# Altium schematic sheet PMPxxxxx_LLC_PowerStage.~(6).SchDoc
size 431 x 279 mm; Date: Not shown in title block; ApprovedBy: Not shown in title block; CheckedBy: Not shown in title block; Author: Not shown in title block; CompanyName: Not shown in title block; Engineer: Not shown in title block; Organization: Not shown in title block; Address1: Not shown in title block; Address2: Not shown in title block; Address3: Not shown in title block; Address4: Not shown in title block; DocumentNumber: 2; Revision: Use project parameter SCH_Rev; SheetNumber: 2; SheetTotal: 4; PageSetup: Record=PageOptions¦CenterHorizontal=True¦CenterVertical=True¦PrintScale=1.00¦XCorrection=1.00¦YCorrection=1.00¦PrintKind=0¦BorderSize=5000000¦LeftOffset=0¦BottomOffset=0¦Orientation=2¦PaperLength=1000¦PaperWidth=1000¦Scale=100¦PaperSource=15¦PrintQuality=600¦MediaType=1¦DitherType=10¦PaperKind=Letter¦PrintScaleMode=1
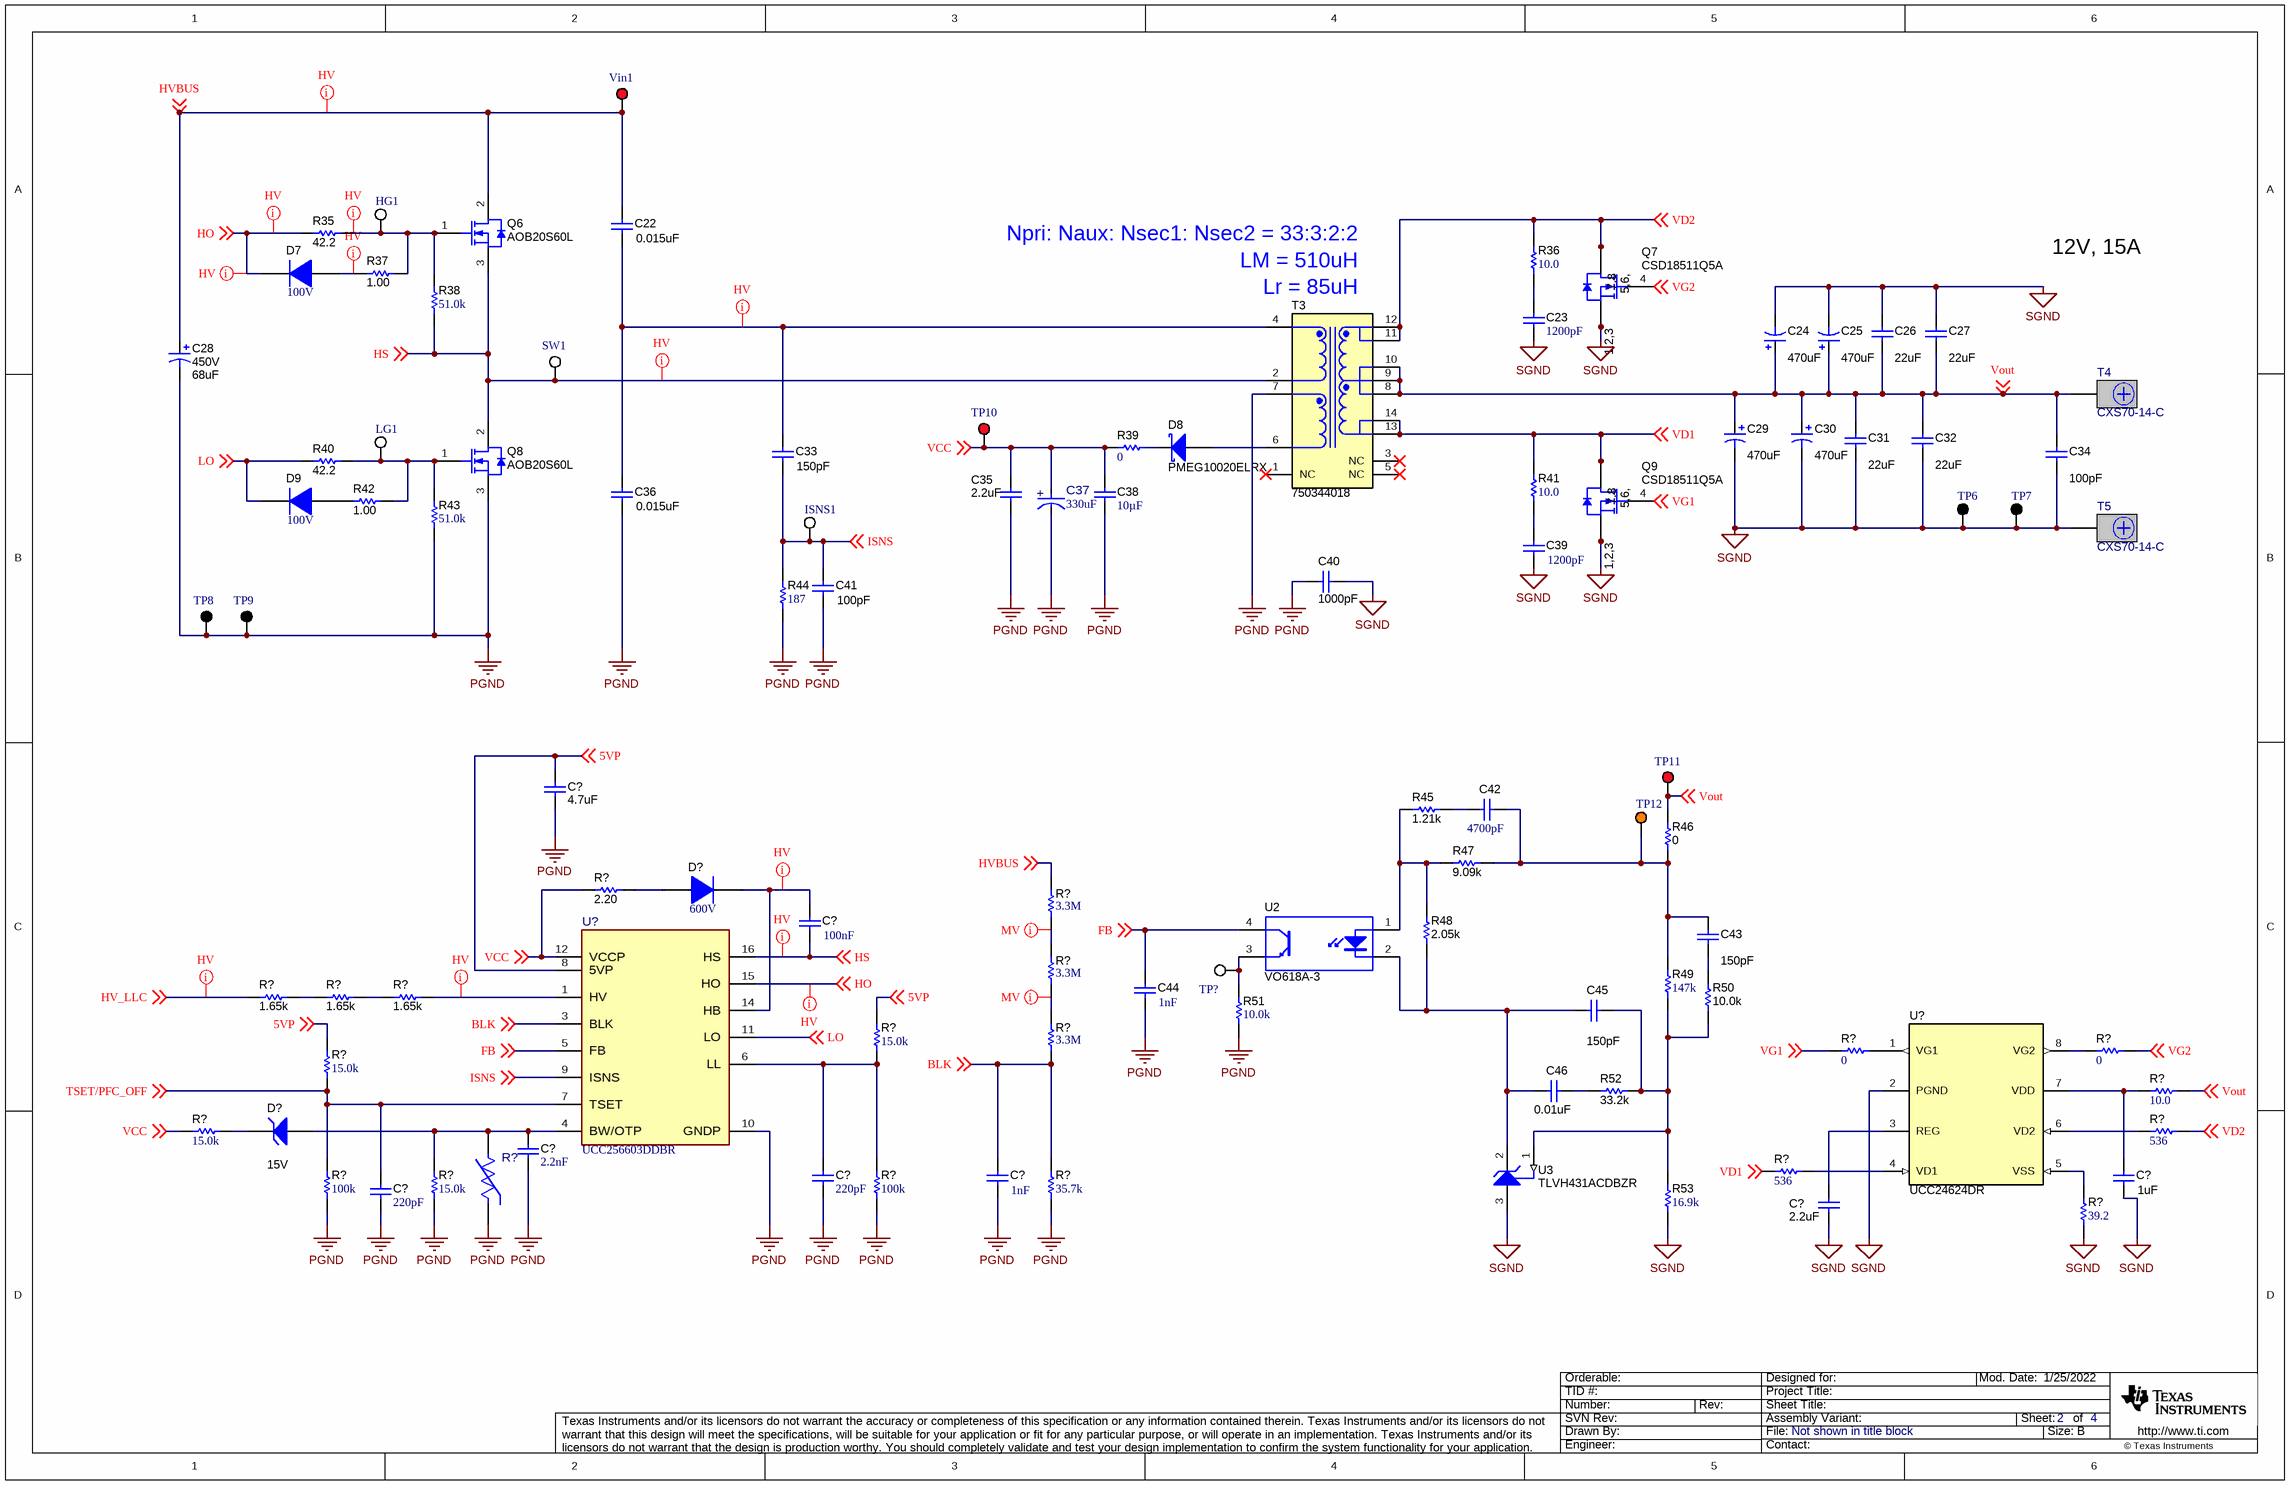
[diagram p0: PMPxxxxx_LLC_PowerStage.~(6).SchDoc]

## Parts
(Parts that share a designator on the sheet are numbered #1, #2 ... from top to bottom, then left to right.)
C22  ValueDisplayed: 0.015uF  [B32652_1800x700x1250]  (hidden comment: B32652A7153J000)
C23  ValueDisplayed: 1200pF  [0805L]  (hidden comment: GRM2165C2A122JA01D)
C24  ValueDisplayed: 470uF  [HW_1000x1600]  (hidden comment: UHW1V471MPD)
C25  ValueDisplayed: 470uF  [HW_1000x1600]  (hidden comment: UHW1V471MPD)
C26  ValueDisplayed: 22uF  [1206_190L]  (hidden comment: C3216X5R1E226M160AB)
C27  ValueDisplayed: 22uF  [1206_190L]  (hidden comment: C3216X5R1E226M160AB)
C28  VDC_V: 450V  ValueDisplayed: 68uF  [KXG_1800x3150]  (hidden comment: EKXG451ELL680MMN3S)
C29  ValueDisplayed: 470uF  [HW_1000x1600]  (hidden comment: UHW1V471MPD)
C30  ValueDisplayed: 470uF  [HW_1000x1600]  (hidden comment: UHW1V471MPD)
C31  ValueDisplayed: 22uF  [1206_190L]  (hidden comment: C3216X5R1E226M160AB)
C32  ValueDisplayed: 22uF  [1206_190L]  (hidden comment: C3216X5R1E226M160AB)
C33  ValueDisplayed: 150pF  [1206L]  (hidden comment: GRM31A5C2J151JW01D)
C34  ValueDisplayed: 100pF  [0603L]  (hidden comment: 06035A101FAT2A)
C35  ValueDisplayed: 2.2uF  [0805L]  (hidden comment: C2012X7R1V225K085AC)
C36  ValueDisplayed: 0.015uF  [B32652_1800x700x1250]  (hidden comment: B32652A7153J000)
C37  ValueDisplayed: 330uF  [FP-35ZL330MEFC10X16_RADIAL-MFG]  (hidden comment: 35ZL330MEFC10X16)
C38  ValueDisplayed: 10µF  [1206_180]  (hidden comment: C1206C106J3RACAUTO)
C39  ValueDisplayed: 1200pF  [0805L]  (hidden comment: GRM2165C2A122JA01D)
C40  ValueDisplayed: 1000pF  [CD45_700x600x1100]  (hidden comment: CD45-E2GA102M-NKA)
C41  ValueDisplayed: 100pF  [1206L]  (hidden comment: 12061A101JAT2A)
C42  ValueDisplayed: 4700pF  [0603L]  (hidden comment: C0603C472J1GAC7867)
C43  ValueDisplayed: 150pF  [0402L]  (hidden comment: 885012005062)
C44  Cap_F: 1nF  [1206L]  (hidden comment: 12061A102JAT2A)
C45  ValueDisplayed: 150pF  [0402L]  (hidden comment: 885012005062)
C46  ValueDisplayed: 0.01uF  [0603L]  (hidden comment: 06031C103JAT2A)
C?#1  ValueDisplayed: 4.7uF  [1206L]  (hidden comment: C3216X7R1E475K085AB)
C?#2  Cap_F: 100nF  [1206_180L]  (hidden comment: GRM31C5C1E104JA01L)
C?#3  Cap_F: 2.2nF  [0603]  (hidden comment: C0603X222K5RACTU)
C?#4  Cap_F: 220pF  [0603]  (hidden comment: C0603X221K5RACTU)
C?#5  Cap_F: 1nF  [0402L]  (hidden comment: 04025C102JAT2A)
C?#6  ValueDisplayed: 1uF  [0603L]  (hidden comment: GRM188R71C105KE15D)
C?#7  Cap_F: 220pF  [0603]  (hidden comment: C0603X221K5RACTU)
C?#8  ValueDisplayed: 2.2uF  [0805L]  (hidden comment: C2012X7R1V225K085AC)
D7  Vr_V: 100V  [SOD-123]  (hidden comment: 1N4148W-7-F)
D8  PMEG10020ELRX  [SOD-123W]
D9  Vr_V: 100V  [SOD-123]  (hidden comment: 1N4148W-7-F)
D?#1  Vr_V: 600V  [SMAF]  (hidden comment: ES1JAF)
D?#2  value 15V  [SOD-123]  (hidden comment: DDZ15-7)
HG1  5012  [Keystone5012]  (value not drawn)
ISNS1  5012  [Keystone5012]  (value not drawn)
LG1  5012  [Keystone5012]  (value not drawn)
Q6  AOB20S60L  [DDPAK]
Q7  CSD18511Q5A  [DQJ0008A]
Q8  AOB20S60L  [DDPAK]
Q9  CSD18511Q5A  [DQJ0008A]
R35  ValueDisplayed: 42.2  [0603]  (hidden comment: RC0603FR-0742R2L)
R36  ValueDisplayed: 10.0  [1206L]  (hidden comment: RC1206FR-0710RL)
R37  ValueDisplayed: 1.00  [0603L]  (hidden comment: RC0603FR-071RL)
R38  ValueDisplayed: 51.0k  [0603L]  (hidden comment: RC0603FR-0751KL)
R39  ValueDisplayed: 0  [1206L]  (hidden comment: ERJ-8GEY0R00V)
R40  ValueDisplayed: 42.2  [0603L]  (hidden comment: RC0603FR-0742R2L)
R41  ValueDisplayed: 10.0  [1206L]  (hidden comment: RC1206FR-0710RL)
R42  ValueDisplayed: 1.00  [0603L]  (hidden comment: RC0603FR-071RL)
R43  ValueDisplayed: 51.0k  [0603L]  (hidden comment: RC0603FR-0751KL)
R44  ValueDisplayed: 187  [1206]  (hidden comment: RC1206FR-07187RL)
R45  ValueDisplayed: 1.21k  [0603L]  (hidden comment: RC0603FR-071K21L)
R46  ValueDisplayed: 0  [0402L]  (hidden comment: RC0402JR-070RL)
R47  ValueDisplayed: 9.09k  [0603L]  (hidden comment: RC0603FR-079K09L)
R48  ValueDisplayed: 2.05k  [0603L]  (hidden comment: RC0603FR-072K05L)
R49  ValueDisplayed: 147k  [0603L]  (hidden comment: RC0603FR-07147KL)
R50  ValueDisplayed: 10.0k  [0603L]  (hidden comment: ERJ-3EKF1002V)
R51  ValueDisplayed: 10.0k  [0402L]  (hidden comment: ERJ-2RKF1002X)
R52  ValueDisplayed: 33.2k  [0603L]  (hidden comment: RC0603FR-0733K2L)
R53  ValueDisplayed: 16.9k  [0603L]  (hidden comment: RC0603FR-0716K9L)
R?#1  ValueDisplayed: 2.20  [0603L]  (hidden comment: ERJ-3RQF2R2V)
R?#2  Res_ohm: 3.3M  [FP-KTR18EZPF3304_1206-MFG]  (hidden comment: KTR18EZPF3304)
R?#3  Res_ohm: 3.3M  [FP-KTR18EZPF3304_1206-MFG]  (hidden comment: KTR18EZPF3304)
R?#4  ValueDisplayed: 1.65k  [1206L]  (hidden comment: CRCW12061K65FKEA)
R?#5  ValueDisplayed: 1.65k  [1206L]  (hidden comment: CRCW12061K65FKEA)
R?#6  ValueDisplayed: 1.65k  [1206L]  (hidden comment: CRCW12061K65FKEA)
R?#7  ValueDisplayed: 15.0k  [0603]  (hidden comment: RT0603BRD0715KL)
R?#8  Res_ohm: 3.3M  [FP-KTR18EZPF3304_1206-MFG]  (hidden comment: KTR18EZPF3304)
R?#9  ValueDisplayed: 0  [0603L]  (hidden comment: RC0603JR-070RL)
R?#10  ValueDisplayed: 0  [0603L]  (hidden comment: RC0603JR-070RL)
R?#11  ValueDisplayed: 15.0k  [0603]  (hidden comment: RT0603BRD0715KL)
R?#12  ValueDisplayed: 10.0  [0603L]  (hidden comment: RC0603FR-0710RL)
R?#13  ValueDisplayed: 15.0k  [0603]  (hidden comment: RG1608P-153-B-T5)
R?#14  ValueDisplayed: 536  [0603L]  (hidden comment: RT0603BRD07536RL)
R?#15  ValueDisplayed: 536  [0603L]  (hidden comment: RT0603BRD07536RL)
R?#16  ValueDisplayed: 100k  [0603]  (hidden comment: RT0603BRD07100KL)
R?#17  ValueDisplayed: 15.0k  [0603]  (hidden comment: RG1608P-153-B-T5)
R?#18  ValueDisplayed: 100k  [0603]  (hidden comment: RT0603BRD07100KL)
R?#19  ValueDisplayed: 35.7k  [0603]  (hidden comment: RT0603BRD0735K7L)
R?#20  ValueDisplayed: 39.2  [0603L]  (hidden comment: RC0603FR-0739R2L)
R?#21  B57371V2474J060  [FP-B57371V2474J060_0603-MFG]  (value not drawn)
SW1  5012  [Keystone5012]  (value not drawn)
T3  750344018  [Wurth_750344018]
T4  CXS70-14-C  [Panduit_CXS70-14-C]
T5  CXS70-14-C  [Panduit_CXS70-14-C]
TP6  5011  [Keystone5011]  (value not drawn)
TP7  5011  [Keystone5011]  (value not drawn)
TP8  5011  [Keystone5011]  (value not drawn)
TP9  5011  [Keystone5011]  (value not drawn)
TP10  5010  [Keystone5010]  (value not drawn)
TP11  5010  [Keystone5010]  (value not drawn)
TP12  5013  [Keystone5013]  (value not drawn)
TP?  5012  [Keystone5012]  (value not drawn)
U2  VO618A-3  [DIP-4]
U3  TLVH431ACDBZR  [DBZ0003A_N]
U?#1  UCC256603DDBR  [DDB0014A-MFG]
U?#2  UCC24624DR  [D0008A_N]
Vin1  5010  [Keystone5010]  (value not drawn)

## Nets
PGND: C28.2(-) C35.2 C36.2 C37.1(CATHODE) C38.2 C40.2 C41.2 C44.2 C?#1.2 C?#3.2 C?#4.2 C?#5.2 C?#7.2 Q8.3(S) R43.1 R44.1 R51.1 R?#16.1 R?#17.1 R?#18.1 R?#19.1 R?#21.1 T3.7 TP8.1 TP9.1 U?#1.10(GNDP)
SGND: C23.2 C24.2(-) C25.2(-) C26.1 C27.1 C29.2(-) C30.2(-) C31.2 C32.2 C34.2 C39.2 C40.1 C?#6.2 C?#8.2 Q7.1(S) Q7.2(S) Q7.3(S) Q9.1(S) Q9.2(S) Q9.3(S) R53.1 R?#20.2 T5.1 TP6.1 TP7.1 U3.3(ANODE) U?#2.2(PGND)
5VP: C?#1.1 R?#7.2 R?#11.2 U?#1.8(5VP) ; off-sheet 5VP
BLK: C?#5.1 R?#8.1 R?#19.2 U?#1.3(BLK) ; off-sheet BLK
FB: C44.1 U2.4(C) U?#1.5(FB) ; off-sheet FB
HO: D7.1(K) R35.1 U?#1.15(HO) ; off-sheet HO
HS: C?#2.2 Q6.3(S) Q8.2(D) R38.1 SW1.1 T3.2 U?#1.16(HS) ; off-sheet HS
HV_LLC: R?#4.1 ; off-sheet HV_LLC
HVBUS: C22.1 C28.1(+) Q6.2(D) R?#2.2 Vin1.1 ; off-sheet HVBUS
ISNS: C33.2 C41.1 ISNS1.1 R44.2 U?#1.9(ISNS) ; off-sheet ISNS
LO: D9.1(K) R40.1 U?#1.11(LO) ; off-sheet LO
TSET/PFC_OFF: C?#7.1 R?#11.1 R?#16.2 U?#1.7(TSET) ; off-sheet TSET/PFC_OFF
VCC: C35.1 C37.2(ANODE) C38.1 R39.1 R?#1.1 R?#13.2 TP10.1 U?#1.12(VCCP) ; off-sheet VCC
VD1: Q9.5(D) Q9.6(D) Q9.7(D) Q9.8(D) Q9.9(D) R41.2 R?#15.2 T3.13 T3.14 ; off-sheet VD1
VD2: Q7.5(D) Q7.6(D) Q7.7(D) Q7.8(D) Q7.9(D) R36.2 R?#14.1 T3.11 T3.12 ; off-sheet VD2
VG1: Q9.4(G) R?#9.1 ; off-sheet VG1
VG2: Q7.4(G) R?#10.2 ; off-sheet VG2
Vout: C24.1(+) C25.1(+) C26.2 C27.2 C29.1(+) C30.1(+) C31.1 C32.1 C34.1 R46.2 R?#12.2 T3.8 T3.9 T3.10 T4.1 TP11.1 ; off-sheet Vout
NetC22_2: C22.2 C33.1 C36.1 T3.4
NetC23_1: C23.1 R36.1
NetC39_1: C39.1 R41.1
NetC42_1: C42.1 C43.1 R46.1 R47.2 R49.2 TP12.1
NetC42_2: C42.2 R45.2
NetC43_2: C43.2 R50.2
NetC45_1: C45.1 R49.1 R50.1 R52.1 R53.2 U3.1(REF)
NetC45_2: C45.2 C46.2 R48.1 U2.2(K) U3.2(CATHODE)
NetC46_1: C46.1 R52.2
NetC?#2_1: C?#2.1 D?#1.1(K) U?#1.14(HB)
NetC?#3_1: C?#3.1 D?#2.2(A) R?#17.2 R?#21.2 U?#1.4(BW/OTP)
NetC?#4_1: C?#4.1 R?#7.1 R?#18.2 U?#1.6(LL)
NetC?#6_1: C?#6.1 R?#12.1 U?#2.7(VDD)
NetC?#8_1: C?#8.1 U?#2.3(REG)
NetD7_2: D7.2(A) R37.1
NetD8_1: D8.1(K) R39.2
NetD8_2: D8.2(A) T3.6
NetD9_2: D9.2(A) R42.1
NetD?#1_2: D?#1.2(A) R?#1.2
NetD?#2_1: D?#2.1(K) R?#13.1
NetHG1_1: HG1.1 Q6.1(G) R35.2 R37.2 R38.2
NetLG1_1: LG1.1 Q8.1(G) R40.2 R42.2 R43.2
NetR45_1: R45.1 R47.1 R48.2 U2.1(A)
NetR51_2: R51.2 TP?.1 U2.3(E)
NetR?#2_1: R?#2.1 R?#3.2
NetR?#3_1: R?#3.1 R?#8.2
NetR?#4_2: R?#4.2 R?#5.1
NetR?#5_2: R?#5.2 R?#6.1
NetR?#6_2: R?#6.2 U?#1.1(HV)
NetR?#9_2: R?#9.2 U?#2.1(VG1)
NetR?#10_1: R?#10.1 U?#2.8(VG2)
NetR?#14_2: R?#14.2 U?#2.6(VD2)
NetR?#15_1: R?#15.1 U?#2.4(VD1)
NetR?#20_1: R?#20.1 U?#2.5(VSS)

Not connected (* = marked no-connect by the designer): T3 1(NC)* 3(NC)* 5(NC)*

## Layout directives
net class HV: HO, HS, HV_LLC, HVBUS, NetC22_2, NetC?#2_1, NetD7_2, NetHG1_1, NetR?#6_2
net class MV: NetR?#2_1, NetR?#3_1

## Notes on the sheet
- Npri: Naux: Nsec1: Nsec2 = 33:3:2:2
- LM = 510uH
- (near T3) Lr = 85uH
- 12V, 15A

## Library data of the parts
C22 C36 = CMP-0012346-3: CAP, Film, 0.015 uF, 1250 V, +/- 5%, AEC-Q200 Grade 3, TH; Manufacturer: TDK; TaMin_C: -55°C; Polarized: N; SizeAreaWB_mm2: 180; Value1: Unknown; TaMax_C: 100°C; SizeZ_mm: 12.5; SizeX_mm: 18; SizeY_mm: 7; Cap_Case: 18x7x12.5; Value2: 1250V; SizeArea_mm2: 126; CompType: Capacitor; AEC Qualified: Y; Cap_F: 15nF; VDC_V: 1.25kV; AEC Grade: 3; AEC Category: Q200
C23 C39 = CMP-0008098-2: CAP, CERM, 1200 pF, 100 V, +/- 5%, C0G/NP0, 0805; Manufacturer: MuRata; TaMin_C: -55°C; Polarized: N; SizeAreaWB_mm2: 6.75; Value1: Unknown; U/M: EA; Value: 1200pF; TaMax_C: 125°C; SizeZ_mm: 1.45; SizeX_mm: 2; SizeY_mm: 1.25; Cap_Case: 0805; Value2: 100V; SizeArea_mm2: 2.5; Cap_F: 1.2nF; AEC Category: Q200
C24 C25 C29 C30 = CMP-0010541-2: CAP, AL, 470 uF, 35 V, +/- 20%, 0.03 ohm, TH; Manufacturer: Nichicon; TaMin_C: -40°C; ESR_ohm: 0.03; Polarized: Y; SizeAreaWB_mm2: 144; U/M: EA; Value: 470uF; TaMax_C: 105°C; SizeZ_mm: 17.5; SizeX_mm: 10; Cap_Case: 10x16mm; Value2: 35V; SizeArea_mm2: 100; CompType: Capacitor; AEC Qualified: N; Cap_F: 470µF; IRMS_A: 2A; AEC Category: Q200
C26 C27 C31 C32 = CMP-0008654-2: CAP, CERM, 22 uF, 25 V, +/- 20%, X5R, 1206_190; Manufacturer: TDK; TaMin_C: -55°C; Polarized: N; SizeAreaWB_mm2: 10.92; Value1: Unknown; U/M: EA; Value: 22uF; TaMax_C: 85°C; SizeZ_mm: 1.9; SizeX_mm: 3.2; SizeY_mm: 1.6; Cap_Case: 1206; Value2: 25V; SizeArea_mm2: 5.12; CompType: Capacitor; Cap_F: 22µF; AEC Category: Q200
C28 = CMP-0010043-2: CAP, AL, 68 uF, 450 V, +/- 20%, TH; Manufacturer: Chemi-Con; TaMin_C: -25°C; Polarized: Y; SizeAreaWB_mm2: 400; Value1: Unknown; U/M: EA; Value: 68uF; TaMax_C: 105°C; SizeZ_mm: 33; SizeX_mm: 18; Cap_Case: 18x31.5mm; SizeArea_mm2: 324; CompType: Capacitor; Cap_F: 68µF; IRMS_A: 6.3dA; AEC Category: Q200
C33 = CMP-0008885-2: CAP, CERM, 150 pF, 630 V, +/- 5%, C0G/NP0, 1206; Manufacturer: MuRata; TaMin_C: -55°C; Polarized: N; SizeAreaWB_mm2: 10.92; Value1: Unknown; U/M: EA; Value: 150pF; TaMax_C: 125°C; SizeZ_mm: 1.35; SizeX_mm: 3.2; SizeY_mm: 1.6; Cap_Case: 1206; Value2: 630V; SizeArea_mm2: 5.12; CompType: Capacitor; AEC Category: Q200
C34 = CMP-0006762-4: CAP, CERM, 100 pF, 50 V, +/- 1%, C0G/NP0, 0603; Manufacturer: AVX; TaMin_C: -55°C; Polarized: N; SizeAreaWB_mm2: 4.68; Value1: Unknown; U/M: EA; TaMax_C: 125°C; SizeZ_mm: 1; SizeX_mm: 1.6; SizeY_mm: 0.8; Cap_Case: 0603; Value2: 50V; SizeArea_mm2: 1.28; CompType: Capacitor; Value: 100pF; AEC Category: Q200
C35 C?#8 = CMP-0007883-2: CAP, CERM, 2.2 uF, 35 V, +/- 10%, X7R, 0805; Manufacturer: TDK; TaMin_C: -55°C; Polarized: N; SizeAreaWB_mm2: 6.75; Value1: Unknown; U/M: EA; Value: 2.2uF; TaMax_C: 125°C; SizeZ_mm: 1.45; SizeX_mm: 2; SizeY_mm: 1.25; Cap_Case: 0805; Value2: 35V; SizeArea_mm2: 2.5; CompType: Capacitor; Cap_F: 2.2µF; AEC Category: Q200
C37 = CMP-0098283-1: Cap Aluminum Lytic 330uF 35V 20% (10 X 16mm) Radial 5mm 1430mA 4000h 105C Bulk; Manufacturer: Rubycon; AEC Qualified: No; Cap_F: 330µF; IRMS_A: 1.43A; SizeZ_mm: 17.5mm; Dissipation Factor: 12%; Leakage Current: 115.5uA; Life: 4000Hours; Value: 330µF
C38 = CMP-0081062-1: CAP, CERM, 10 µF, 25 V,+/- 5%, X7R, AEC-Q200 Grade 1, 1206; Manufacturer: Kemet; TaMin_C: -55°C; Polarized: N; SizeAreaWB_mm2: 10.92; U/M: EA; Value: 10uF; TaMax_C: 125°C; SizeZ_mm: 1.8; SizeX_mm: 3.2; SizeY_mm: 1.6; Value2: 25V; SizeArea_mm2: 5.12; AEC Qualified: Y; AEC Grade: 1; AEC Category: Q200
C40 = CMP-0009595-2: CAP, CERM, 1000 pF,  V, +/- 20%, E, D7xT6mm; Manufacturer: TDK; TaMin_C: -25°C; Polarized: N; SizeAreaWB_mm2: 101.2; Value1: Unknown; U/M: EA; Value: 1000pF; TaMax_C: 125°C; SizeZ_mm: 11; SizeX_mm: 10.65; SizeY_mm: 6; Cap_Case: 7x6x11mm; SizeArea_mm2: 63.9; Cap_F: 1nF; AEC Category: Q200
C41 = CMP-0008462-2: CAP, CERM, 100 pF, 100 V, +/- 5%, C0G/NP0, 1206; Manufacturer: AVX; TaMin_C: -55°C; ESR_ohm: 7.01d; Polarized: N; SizeAreaWB_mm2: 10.92; Value1: 0.701 ohm; U/M: EA; Value: 100pF; TaMax_C: 125°C; SizeZ_mm: 1.35; SizeX_mm: 3.2; SizeY_mm: 1.6; Cap_Case: 1206; Value2: 100V; SizeArea_mm2: 5.12; CompType: Capacitor; AEC Category: Q200
C42 = CMP-0006941-4: CAP, CERM, 4700 pF, 100 V, +/- 5%, C0G/NP0, 0603; Manufacturer: Kemet; TaMin_C: -55°C; Polarized: N; SizeAreaWB_mm2: 4.68; Value1: Unknown; U/M: EA; Value: 4700pF; TaMax_C: 125°C; SizeZ_mm: 1; SizeX_mm: 1.6; SizeY_mm: 0.8; Cap_Case: 0603; Value2: 100V; SizeArea_mm2: 1.28; Cap_F: 4.7nF; AEC Category: Q200
C43 C45 = CMP-0064913-2: CAP, CERM, 150 pF, 50 V,+/- 5%, C0G/NP0, 0402; Manufacturer: Wurth Elektronik; TaMin_C: -55°C; Polarized: N; SizeAreaWB_mm2: 3; Value1: Unknown; U/M: EA; Value: 150pF; TaMax_C: 125°C; SizeZ_mm: 0.6; SizeX_mm: 1; SizeY_mm: 0.5; Cap_Case: 0402; Value2: 50V; CompType: Capacitor; AEC Category: Q200
C44 = CMP-0008465-2: CAP, CERM, 1000 pF, 100 V, +/- 5%, C0G/NP0, 1206; Manufacturer: AVX; TaMin_C: -55°C; ESR_ohm: 2.38d; Polarized: N; SizeAreaWB_mm2: 10.92; Value1: 0.238 ohm; U/M: EA; Value: 1000pF; TaMax_C: 125°C; SizeZ_mm: 1.35; SizeX_mm: 3.2; SizeY_mm: 1.6; Cap_Case: 1206; Value2: 100V; SizeArea_mm2: 5.12; AEC Category: Q200
C46 = CMP-0006726-4: CAP, CERM, 0.01 uF, 100 V, +/- 5%, X7R, 0603; Manufacturer: AVX; TaMin_C: -55°C; ESR_ohm: 0.098; Polarized: N; SizeAreaWB_mm2: 4.68; Value1: 0.098 ohm; U/M: EA; Value: 0.01uF; TaMax_C: 125°C; SizeZ_mm: 1; SizeX_mm: 1.6; SizeY_mm: 0.8; Cap_Case: 0603; Value2: 100V; SizeArea_mm2: 1.28; Cap_F: 10nF; AEC Category: Q200
C?#1 = CMP-0008693-2: CAP, CERM, 4.7 uF, 25 V, +/- 10%, X7R, 1206; Manufacturer: TDK; TaMin_C: -55°C; Polarized: N; SizeAreaWB_mm2: 10.92; Value1: Unknown; U/M: EA; Value: 4.7uF; TaMax_C: 125°C; SizeZ_mm: 1.35; SizeX_mm: 3.2; SizeY_mm: 1.6; Cap_Case: 1206; Value2: 25V; SizeArea_mm2: 5.12; CompType: Capacitor; Cap_F: 4.7µF; AEC Category: Q200
C?#2 = CMP-0064950-2: CAP, CERM, 0.1 uF, 25 V,+/- 5%, C0G/NP0, 1206; Manufacturer: MuRata; TaMin_C: -55°C; Polarized: N; SizeAreaWB_mm2: 10.92; Value1: Unknown; U/M: EA; Value: 0.1uF; TaMax_C: 125°C; SizeZ_mm: 1.8; SizeX_mm: 3.2; SizeY_mm: 1.6; Cap_Case: 1206; Value2: 25V; SizeArea_mm2: 5.12; AEC Category: Q200
C?#3 = CMP-0006983-4: CAP, CERM, 2200 pF, 50 V, +/- 10%, X7R, 0603; Manufacturer: Kemet; TaMin_C: -55°C; Polarized: N; SizeAreaWB_mm2: 4.68; Value1: Unknown; U/M: EA; Value: 2200pF; TaMax_C: 125°C; SizeZ_mm: 1; SizeX_mm: 1.6; SizeY_mm: 0.8; Value2: 50V; SizeArea_mm2: 1.28; AEC Category: Q200
C?#4 C?#7 = CMP-0006982-4: CAP, CERM, 220 pF, 50 V, +/- 10%, X7R, 0603; Manufacturer: Kemet; TaMin_C: -55°C; Polarized: N; SizeAreaWB_mm2: 4.68; Value1: Unknown; U/M: EA; Value: 220pF; TaMax_C: 125°C; SizeZ_mm: 1; SizeX_mm: 1.6; SizeY_mm: 0.8; Value2: 50V; SizeArea_mm2: 1.28; AEC Category: Q200
C?#5 = CMP-0861060-1: CAP, CERM, 1000 pF, 50 V,+/- 5%, X7R, 0402; Manufacturer: AVX; Value2: 50V; SizeY_mm: 0.5; AEC Category: Q200; Polarized: N; Green_Lifecycle: Active; SizeAreaWB_mm2: 3; ValueDisplayed: 1000pF; Cap_Case: 0402; Value: 1000pF; TaMin_C: -55°C; U/M: EA; Green_REACh: Passed; SizeZ_mm: 0.6; SizeX_mm: 1; TaMax_C: 125°C
C?#6 = CMP-0007380-4: CAP, CERM, 1 uF, 16 V, +/- 10%, X7R, 0603; Manufacturer: MuRata; TaMin_C: -55°C; Polarized: N; SizeAreaWB_mm2: 4.68; Value1: Unknown; U/M: EA; Value: 1uF; TaMax_C: 125°C; SizeZ_mm: 1; SizeX_mm: 1.6; SizeY_mm: 0.8; Cap_Case: 0603; Value2: 16V; SizeArea_mm2: 1.28; CompType: Capacitor; Cap_F: 1µF; AEC Category: Q200
D7 D9 = CMP-0029001-2: Diode, Ultrafast, 100 V, 0.15 A, SOD-123; Manufacturer: Diodes Inc.; Io_A: 150mA; Green_Lifecycle: Active; SizeAreaWB_mm2: 13.095; Green_REACh: Passed; Value1: 0.15A; TJmax_C: 150°C; Value: 100V; SizeZ_mm: 1.35; SizeX_mm: 3.85; SizeY_mm: 1.7; Vf_V: 1.25V; SizeArea_mm2: 6.545; AEC Category: Q101
D8 = CMP-0028977-2: Diode, Schottky, 100 V, 2 A, AEC-Q101, SOD-123W; Manufacturer: Nexperia; Io_A: 2A; SizeAreaWB_mm2: 12.15; Vr_V: 100V; TJmax_C: 175°C; Value: 100V; SizeZ_mm: 1; SizeX_mm: 3.5; SizeY_mm: 1.7; Vf_V: 830mV; Value2: 0.83V; SizeArea_mm2: 5.95; AEC Qualified: Y; AEC Category: Q101
D?#1 = CMP-0029162-2: Diode, Ultrafast, 600 V, 1 A, AEC-Q101, SMAF; Manufacturer: Fairchild Semiconductor; Io_A: 1A; Green_Lifecycle: Not Set; SizeAreaWB_mm2: 19.95; Green_REACh: Incomplete; TJmax_C: 150°C; Value: 600V; SizeZ_mm: 1; SizeX_mm: 4.7; SizeY_mm: 2.5; Vf_V: 1.7V; SizeArea_mm2: 11.75; AEC Qualified: Y; AEC Category: Q101
D?#2 = CMP-0085135-1: Diode, Zener, 15 V, 500 mW, SOD-123; Manufacturer: Diodes Inc.; SizeAreaWB_mm2: 13.095; SizeArea_mm2: 6.545; SizeY_mm: 1.7; AEC Qualified: N; SizeZ_mm: 1.35; Value1: 0.5W; SizeX_mm: 3.85; Power_W: 500mW; RJA_CperW: 425; AEC Category: Q101
HG1 ISNS1 LG1 SW1 TP? = CMP-0055149-2: Test Point, Multipurpose, White, TH; Manufacturer: Keystone Electronics; CNHeader: FALSE; Green_Lifecycle: Active; Green_REACh: Passed; ContactFinish: Silver; CT: TRUE
Q6 Q8 = CMP-0001135-4: MOSFET, N-CH, 600 V, 20 A, DDPAK; Alternate Manufacturer: None; Manufacturer: AOS; SizeZ_mm: 4.445; ChType: N; Value2: 19.8 nC; VdsMax_V: 600V; SizeX_mm: 15.245; SizeAreaWB_mm2: 209.6992; SizeY_mm: 10.16; Vgs_V: 30V; QgTyp_nC: 19.8; Value: 600V; SizeArea_mm2: 154.8892; AEC Category: Q101; IdsMax_A: 20A; ChMode: Enhancement
Q7 Q9 = CMP-0000711-1: MOSFET, N-CH, 40 V, 100 A, DQJ0008A (VSONP-8); Alternate Manufacturer: None; Manufacturer: Texas Instruments; SizeZ_mm: 1.1; ChType: N; Value2: 63 nC; Value1: 0.003; VdsMax_V: 40V; SizeX_mm: 6; SizeY_mm: 4.9; Vgs_V: 20V; Value: 40V; Rdson45_ohm: 3.5m; SizeArea_mm2: 29.4; AEC Category: Q101; IdsMax_A: 100A; SizeAreaWB_mm2: 55.2; U/M: EA; QgTyp_nC: 63
R35 R40 = CMP-0023107-5: RES, 42.2, 1%, 0.1 W, 0603; Manufacturer: Yageo; Power_W: 100mW; TempCo: 100 ppm/C; Value_Code: 42R2; Value: 42.2; EIA_Code: E96; SizeX_mm: 1.6; SizeY_mm: 0.8; SizeZ_mm: 1; Value2: 0.1W; SizeArea_mm2: 1.28; CompType: Resistor; AEC Qualified: N; VDC_V: 75V; AEC Category: Q200; SizeAreaWB_mm2: 4.68
R36 R41 = CMP-0017851-2: RES, 10.0, 1%, 0.25 W, 1206; Manufacturer: Yageo America; Power_W: 250mW; TempCo: 200 ppm/C; Value_Code: 10R0; U/M: EA; Value: 10.0; EIA_Code: E96; Res_ohm: 10; SizeX_mm: 3.2; SizeY_mm: 1.6; SizeZ_mm: 1.35; Value2: 0.25W; SizeArea_mm2: 5.12; VDC_V: 200V; AEC Category: Q200
R37 R42 = CMP-0022900-4: RES, 1.00, 1%, 0.1 W, 0603; Manufacturer: Yageo; Power_W: 100mW; TempCo: 200 ppm/C; Value_Code: 1R00; Value: 1.00; EIA_Code: E96; Res_ohm: 1; SizeX_mm: 1.6; SizeY_mm: 0.8; Value2: 0.1W; SizeArea_mm2: 1.28; CompType: Resistor; AEC Qualified: N; VDC_V: 75V; AEC Category: Q200; SizeAreaWB_mm2: 4.68
R38 R43 = CMP-0023167-5: RES, 51.0 k, 1%, 0.1 W, 0603; Manufacturer: Yageo; Power_W: 100mW; TempCo: 100 ppm/C; Value_Code: 51k0; Value: 51.0k; Res_ohm: 51k; SizeX_mm: 1.6; SizeY_mm: 0.8; SizeZ_mm: 1; Value2: 0.1W; SizeArea_mm2: 1.28; AEC Qualified: N; VDC_V: 75V; AEC Category: Q200; SizeAreaWB_mm2: 4.68
R39 = CMP-0018748-3: RES, 0, 5%, 0.25 W, AEC-Q200 Grade 0, 1206; Manufacturer: Panasonic; Power_W: 250mW; TempCo: 600 ppm/C; Value_Code: 0000; Value: 0; EIA_Code: E24; SizeX_mm: 3.2; SizeY_mm: 1.6; SizeZ_mm: 1.35; Value2: 0.25W; SizeArea_mm2: 5.12; AEC Qualified: Y; VDC_V: 200V; AEC Category: Q200; SizeAreaWB_mm2: 10.92
R44 = CMP-0017949-2: RES, 187, 1%, 0.25 W, 1206; Manufacturer: Yageo America; Power_W: 250mW; TempCo: 100 ppm/C; Value_Code: 187R; U/M: EA; Value: 187; EIA_Code: E96; SizeX_mm: 3.2; SizeY_mm: 1.6; SizeZ_mm: 1.35; Value2: 0.25W; SizeArea_mm2: 5.12; VDC_V: 200V; AEC Category: Q200
R45 = CMP-0022871-5: RES, 1.21 k, 1%, 0.1 W, 0603; Manufacturer: Yageo; Power_W: 100mW; TempCo: 100 ppm/C; Value_Code: 1k21; Value: 1.21k; EIA_Code: E96; SizeX_mm: 1.6; SizeY_mm: 0.8; SizeZ_mm: 1; Value2: 0.1W; SizeArea_mm2: 1.28; AEC Qualified: N; VDC_V: 75V; AEC Category: Q200; SizeAreaWB_mm2: 4.68
R46 = CMP-0027004-2: RES, 0, 5%, 0.063 W, 0402; Manufacturer: Yageo America; Power_W: 63mW; TempCo: 200 ppm/C; Value_Code: 0000; U/M: EA; Value: 0; EIA_Code: E24; SizeX_mm: 1; SizeY_mm: 0.5; SizeZ_mm: 0.6; Value2: 0.063W; CompType: Resistor; VDC_V: 50V; AEC Category: Q200
R47 = CMP-0023332-5: RES, 9.09 k, 1%, 0.1 W, 0603; Manufacturer: Yageo; Power_W: 100mW; TempCo: 100 ppm/C; Value_Code: 9k09; Value: 9.09k; EIA_Code: E96; SizeX_mm: 1.6; SizeY_mm: 0.8; SizeZ_mm: 1; Value2: 0.1W; SizeArea_mm2: 1.28; AEC Qualified: N; VDC_V: 75V; AEC Category: Q200; SizeAreaWB_mm2: 4.68
R48 = CMP-0022981-5: RES, 2.05 k, 1%, 0.1 W, 0603; Manufacturer: Yageo; Power_W: 100mW; TempCo: 100 ppm/C; Value_Code: 2k05; Value: 2.05k; EIA_Code: E96; SizeX_mm: 1.6; SizeY_mm: 0.8; SizeZ_mm: 1; Value2: 0.1W; SizeArea_mm2: 1.28; AEC Qualified: N; VDC_V: 75V; AEC Category: Q200; SizeAreaWB_mm2: 4.68
R49 = CMP-0022800-4: RES, 147 k, 1%, 0.1 W, 0603; Manufacturer: Yageo; Power_W: 100mW; TempCo: 100 ppm/C; Value: 147k; EIA_Code: E96; SizeX_mm: 1.6; SizeY_mm: 0.8; SizeZ_mm: 1; Value2: 0.1W; SizeArea_mm2: 1.28; AEC Qualified: N; VDC_V: 75V; AEC Category: Q200; SizeAreaWB_mm2: 4.68
R50 = CMP-0022684-3: RES, 10.0 k, 1%, 0.1 W, 0603; Manufacturer: Panasonic; Power_W: 100mW; TempCo: 100 ppm/C; Value_Code: 10k0; U/M: EA; Value: 10.0k; EIA_Code: E96; Res_ohm: 10k; SizeX_mm: 1.6; SizeY_mm: 0.8; SizeZ_mm: 1; Value2: 0.1W; SizeArea_mm2: 1.28; CompType: Resistor; VDC_V: 75V; AEC Category: Q200
R51 = CMP-0026658-1: RES, 10.0 k, 1%, 0.1 W, 0402; Manufacturer: Panasonic; Power_W: 100mW; TempCo: 100 ppm/C; Value_Code: 10k0; U/M: EA; Value: 10.0k; EIA_Code: E96; Res_ohm: 10k; SizeX_mm: 1; SizeY_mm: 0.5; SizeZ_mm: 0.6; Value2: 0.1W; VDC_V: 50V; AEC Category: Q200
R52 = CMP-0023036-5: RES, 33.2 k, 1%, 0.1 W, 0603; Manufacturer: Yageo; Power_W: 100mW; TempCo: 100 ppm/C; Value_Code: 33k2; Value: 33.2k; EIA_Code: E96; SizeX_mm: 1.6; SizeY_mm: 0.8; SizeZ_mm: 1; Value2: 0.1W; SizeArea_mm2: 1.28; AEC Qualified: N; VDC_V: 75V; AEC Category: Q200; SizeAreaWB_mm2: 4.68
R53 = CMP-0022830-5: RES, 16.9 k, 1%, 0.1 W, 0603; Manufacturer: Yageo; Power_W: 100mW; TempCo: 100 ppm/C; Value_Code: 16k9; Value: 16.9k; EIA_Code: E96; SizeX_mm: 1.6; SizeY_mm: 0.8; SizeZ_mm: 1; Value2: 0.1W; SizeArea_mm2: 1.28; AEC Qualified: N; VDC_V: 75V; AEC Category: Q200; SizeAreaWB_mm2: 4.68
R?#1 = CMP-0022711-2: RES, 2.20, 1%, 0.1 W, 0603; Manufacturer: Panasonic; Power_W: 100mW; TempCo: 200 ppm/C; Value_Code: 2R20; U/M: EA; Value: 2.20; Res_ohm: 2.2; SizeX_mm: 1.6; SizeY_mm: 0.8; SizeZ_mm: 1; Value2: 0.1W; SizeArea_mm2: 1.28; CompType: Resistor; AEC Category: Q200
R?#2 R?#3 R?#8 = CMP-0087456-2: 3.3 MOhms ±1% 0.25W, 1/4W Chip Resistor 1206 (3216 Metric) Automotive AEC-Q200, High Voltage Thick Film; Manufacturer: Rohm Semiconductor; AEC Qualified: Yes; Power_W: 250mW; SizeZ_mm: 0.65mm; AEC Grade: Grade 0; TempCo: 100ppm/°C; VDC_V: 500V
R?#4-R?#6 = CMP-0016708-3: RES, 1.65 k, 1%, 0.25 W, AEC-Q200 Grade 0, 1206; Manufacturer: Vishay-Dale; Power_W: 250mW; TempCo: 100 ppm/C; Value_Code: 1k65; Value: 1.65k; EIA_Code: E96; SizeX_mm: 3.2; SizeY_mm: 1.6; SizeZ_mm: 1.35; Value2: 0.25W; SizeArea_mm2: 5.12; CompType: Resistor; AEC Qualified: Y; VDC_V: 200V; AEC Category: Q200; AEC Grade: 0
R?#7 R?#11 = CMP-0023780-3: RES, 15.0 k, 0.1%, 0.1 W, 0603; Manufacturer: Yageo America; Power_W: 100mW; TempCo: 25 ppm/C; Value_Code: 15k0; U/M: EA; Value: 15.0k; EIA_Code: E192; Res_ohm: 15k; SizeX_mm: 1.6; SizeY_mm: 0.8; SizeZ_mm: 1; Value2: 0.1W; SizeArea_mm2: 1.28; VDC_V: 75V; AEC Category: Q200
R?#9 R?#10 = CMP-0025885-5: RES, 0, 5%, 0.1 W, 0603; Manufacturer: Yageo; Power_W: 100mW; TempCo: 200 ppm/C; Value_Code: 0000; Value: 0; EIA_Code: E24; SizeX_mm: 1.6; SizeZ_mm: 1; Value2: 0.1W; SizeArea_mm2: 1.28; AEC Qualified: N; VDC_V: 75V; AEC Category: Q200; SizeY_mm: 0.8; SizeAreaWB_mm2: 4.68
R?#12 = CMP-0022751-4: RES, 10.0, 1%, 0.1 W, 0603; Manufacturer: Yageo; Power_W: 100mW; TempCo: 100 ppm/C; Value_Code: 10R0; Value: 10.0; EIA_Code: E96; Res_ohm: 10; SizeX_mm: 1.6; SizeY_mm: 0.8; SizeZ_mm: 1; Value2: 0.1W; SizeArea_mm2: 1.28; AEC Qualified: N; VDC_V: 75V; AEC Category: Q200; SizeAreaWB_mm2: 4.68
R?#13 R?#17 = CMP-0023441-3: RES, 15.0 k, 0.1%, 0.1 W, 0603; Manufacturer: Susumu Co Ltd; Power_W: 100mW; TempCo: 25 ppm/C; Value_Code: 15k0; U/M: EA; Value: 15.0k; EIA_Code: E192; Res_ohm: 15k; SizeX_mm: 1.6; SizeY_mm: 0.8; SizeZ_mm: 1; Value2: 0.1W; SizeArea_mm2: 1.28; VDC_V: 75V; AEC Category: Q200
R?#14 R?#15 = CMP-0024324-2: RES, 536, 0.1%, 0.1 W, 0603; Manufacturer: Yageo America; Power_W: 100mW; TempCo: 25 ppm/C; Value_Code: 536R; U/M: EA; Value: 536; EIA_Code: E192; SizeX_mm: 1.6; SizeY_mm: 0.8; SizeZ_mm: 1; Value2: 0.1W; SizeArea_mm2: 1.28; VDC_V: 75V; AEC Category: Q200
R?#16 R?#18 = CMP-0023630-3: RES, 100 k, 0.1%, 0.1 W, 0603; Manufacturer: Yageo America; Power_W: 100mW; TempCo: 25 ppm/C; U/M: EA; Value: 100k; EIA_Code: E192; SizeX_mm: 1.6; SizeY_mm: 0.8; SizeZ_mm: 1; Value2: 0.1W; SizeArea_mm2: 1.28; VDC_V: 75V; AEC Category: Q200
R?#19 = CMP-0024147-3: RES, 35.7 k, 0.1%, 0.1 W, 0603; Manufacturer: Yageo America; Power_W: 100mW; TempCo: 25 ppm/C; Value_Code: 35k7; U/M: EA; Value: 35.7k; EIA_Code: E192; SizeX_mm: 1.6; SizeY_mm: 0.8; SizeZ_mm: 1; Value2: 0.1W; SizeArea_mm2: 1.28; VDC_V: 75V; AEC Category: Q200
R?#20 = CMP-0023074-4: RES, 39.2, 1%, 0.1 W, 0603; Manufacturer: Yageo; Power_W: 100mW; TempCo: 100 ppm/C; Value_Code: 39R2; Value: 39.2; EIA_Code: E96; SizeX_mm: 1.6; SizeY_mm: 0.8; SizeZ_mm: 1; Value2: 0.1W; SizeArea_mm2: 1.28; AEC Qualified: N; VDC_V: 75V; AEC Category: Q200; SizeAreaWB_mm2: 4.68
R?#21 = CMP-0096703-1: NTC Thermistor 470k 0603 (1608 Metric); Manufacturer: TDK; AEC Qualified: No; Res_ohm: 470kΩ; Power_W: 180mW; B 25 50: 4386K; B 25 100: 4480K; SizeZ_mm: 0.9mm; B 25 85: 4455K; B Tolerance: 3%; Tolerance_%: 5%
T3 = CMP-0081993-1: Transformer, 510 uH, TH; Manufacturer: Wurth Elektronik; SizeAreaWB_mm2: 1732.5; SizeArea_mm2: 1569.5; AEC Qualified: N; Ns2toNp: 0.06; Lp: 510; AEC Category: Q200; Value: 510uH; SizeZ_mm: 26.5; Ind_H: 510µH; SizeY_mm: 43; LeakageInd_H: 85µH; SizeX_mm: 36.5
T4 T5 = CMP-0075010-2: Terminal 70A Lug; Manufacturer: Panduit; CNHeader: False; Green_Lifecycle: Not Set; Green_REACh: Incomplete; CompType: Screw Terminal
TP6 TP7 = CMP-0055148-2: Test Point, Multipurpose, Black, TH; Manufacturer: Keystone Electronics; CNHeader: FALSE; ContactFinish: Silver; Green_REACh: Passed; Green_Lifecycle: Active; CT: TRUE
TP8 TP9 = CMP-0055148-2: Test Point, Multipurpose, Black, TH; Manufacturer: Keystone Electronics; CNHeader: FALSE; Green_Lifecycle: Active; Green_REACh: Passed; ContactFinish: Silver; CT: TRUE
TP10 TP11 Vin1 = CMP-0055147-2: Test Point, Multipurpose, Red, TH; Manufacturer: Keystone Electronics; CNHeader: FALSE; Green_Lifecycle: Active; Green_REACh: Passed; ContactFinish: Silver; CT: TRUE
TP12 = CMP-0055150-2: Test Point, Multipurpose, Orange, TH; Manufacturer: Keystone Electronics; CNHeader: FALSE; Green_Lifecycle: Active; Green_REACh: Passed; ContactFinish: Silver; CT: TRUE
U2 = CMP-0083653-1: Optocoupler, 5.3 kV, 100-200% CTR, SMT; Manufacturer: Vishay-Semiconductor; CTR (Max): 200%; SizeAreaWB_mm2: 71.064; CTR (Min): 100%; SizeZ_mm: 5; SizeX_mm: 8.8; SizeY_mm: 4.58; SizeArea_mm2: 40.304; Voltage_Isolation_Vrms: 5.3kV
U3 = CMP-0033066-1: Low-Voltage Adjustable Precision Shunt Regulator, 129 ppm / degC, 80 mA, 0 to 70 degC, 3-pin SOT-23 (DBZ), Green (RoHS & no Sb/Br); Manufacturer: Texas Instruments; Min Iz for Regulation(uA): 80; VO Adj(Max)(V): 18; VO Adj(Min)(V): 1.24; Rating: Catalog; SubFamily: Shunt Voltage Reference; Temp Coeff(Max)(ppm/ degree C): 129
U?#1 = CMP-0095299-1: 750kHz Wide VIN/VOUT Range LLC Controller Optimized for Light Load Efficiency; Manufacturer: Texas Instruments; Number Of Outputs: 2; TaMax_C: +125°C; Output Type: Other; TJmax_C: +150°C; AEC Qualified: No; Standoff Height: 0.1mm; TaMin_C: -40°C; SizeZ_mm: 1.75mm; Switching Frequency: 30-750kHz; Max Supply Voltage: 18.5V
U?#2 = CMP-0079610-1: High Performance Synchronous Rectifier Driver for LLC Resonant Converter, D0008A (SOIC-8); Alternate Manufacturer: Texas Instruments; SizeAreaWB_mm2: 56.58; SizeZ_mm: 1.75; SizeX_mm: 4.9; SizeY_mm: 6.2; SizeArea_mm2: 30.38; CompType: IC; AEC Qualified: N; AEC Category: Q200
